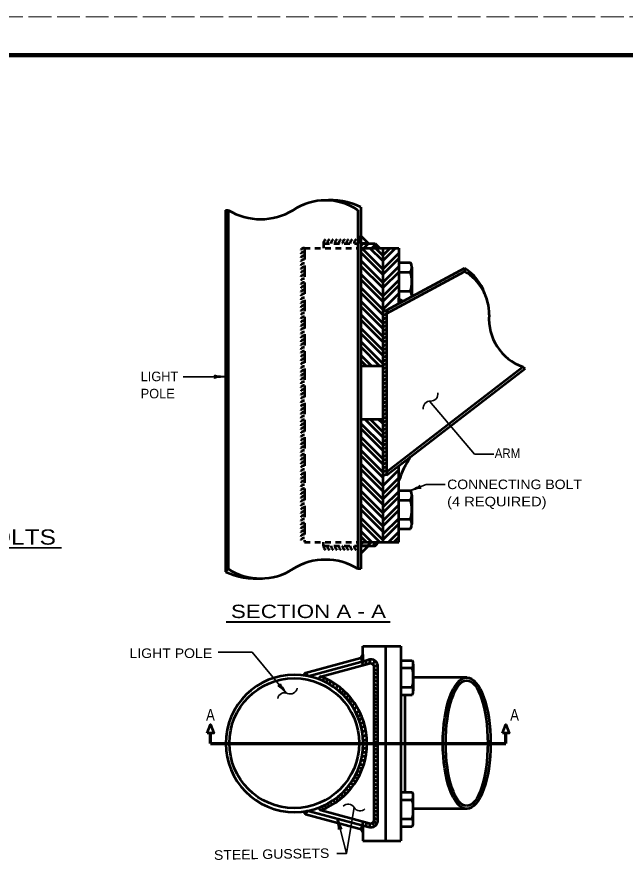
# Model space of a CAD drawing. Extents: x -1 to 679, y -228 to 440.
# Drawn here: x 356 to 515.4, y 218.8 to 440.2 of the extents above; entities that cross this region are included whole.
import ezdxf
from ezdxf.enums import TextEntityAlignment as Align

# ---------------------------------------------------------------- set-up
doc = ezdxf.new("R2010")
doc.units = 0
for name, pattern in [('LONG_DASHED', [7.5, 6, -1.5]), ('MEDIUM_DASHED', [4.5, 3, -1.5]), ('SHORT_DASHED', [2.7, 1.5, -1.2])]:
    doc.linetypes.add(name, pattern=pattern)
doc.layers.add('1', color=7, linetype='Continuous', lineweight=35)
doc.layers.add('61', color=7, linetype='Continuous', lineweight=35)

msp = doc.modelspace()

# ---------------------------------------------------------------- linework, layer by layer
at = {"layer": '1', "lineweight": 53}
for p, q in [((410.626, 389.642), (410.626, 294.892)), ((410.626, 389.642), (411.376, 389.642)), ((411.376, 389.642), (411.376, 295.642)), ((445.376, 389.642), (445.376, 295.642)), ((446.126, 380.892), (449.876, 380.892)), ((446.741, 380.892), (446.148, 380.299)), ((448.156, 380.892), (446.906, 379.642)), ((449.876, 380.892), (451.126, 379.642)), ((446.126, 379.642), (446.126, 295.642)), ((446.126, 379.642), (449.876, 379.642)), ((451.876, 374.173), (446.407, 379.642)), ((451.876, 376.295), (448.529, 379.642)), ((449.876, 380.491), (449.027, 379.642)), ((449.876, 379.642), (451.109, 379.642)), ((451.876, 377.709), (449.943, 379.642)), ((451.126, 379.642), (456.126, 379.642)), ((451.876, 379.642), (451.876, 302.642)), ((455.223, 379.642), (451.876, 376.295)), ((453.809, 379.642), (451.876, 377.709)), ((451.876, 372.759), (446.126, 378.509)), ((456.133, 378.43), (451.876, 374.173)), ((456.134, 377.017), (451.876, 372.759)), ((451.876, 370.638), (446.126, 376.388)), ((451.876, 369.223), (446.126, 374.973)), ((456.134, 374.895), (451.876, 370.638)), ((456.126, 375.892), (459.126, 375.892)), ((459.496, 374.642), (459.496, 367.093)), ((473.295, 374.387), (473.303, 373.544)), ((451.876, 367.102), (446.126, 372.852)), ((456.134, 373.481), (451.876, 369.223)), ((452.884, 362.549), (473.303, 373.544)), ((456.126, 373.392), (459.126, 373.392)), ((451.876, 365.688), (446.126, 371.438)), ((456.134, 371.36), (451.876, 367.102)), ((456.134, 369.945), (451.876, 365.688)), ((451.876, 363.566), (446.126, 369.316)), ((451.876, 362.152), (446.126, 367.902)), ((456.134, 367.824), (451.876, 363.566)), ((456.126, 368.392), (459.126, 368.392)), ((456.126, 368.392), (456.126, 365.142)), ((451.876, 360.031), (446.126, 365.781)), ((456.126, 365.142), (456.126, 366.507)), ((457.386, 365.82), (456.126, 365.142)), ((451.876, 358.616), (446.126, 364.366)), ((452.876, 363.392), (452.876, 320.142)), ((451.876, 356.495), (446.126, 362.245)), ((451.876, 355.081), (446.126, 360.831)), ((451.876, 352.959), (446.126, 358.709)), ((451.876, 351.545), (446.126, 357.295)), ((451.876, 349.424), (446.126, 355.174)), ((451.118, 348.767), (446.126, 353.759)), ((448.997, 348.767), (446.126, 351.638)), ((447.583, 348.767), (446.126, 350.224)), ((451.876, 348.767), (446.126, 348.767)), ((451.876, 334.767), (446.126, 334.767)), ((451.877, 330.145), (447.255, 334.767)), ((451.877, 331.56), (448.669, 334.767)), ((451.876, 333.681), (450.791, 334.767)), ((451.877, 326.61), (446.127, 332.36)), ((451.877, 328.024), (446.408, 333.492)), ((451.877, 324.488), (446.127, 330.238)), ((451.877, 323.074), (446.127, 328.824)), ((451.877, 320.953), (446.127, 326.703)), ((451.877, 319.538), (446.127, 325.288)), ((451.877, 317.417), (446.127, 323.167)), ((451.877, 316.003), (446.127, 321.753)), ((451.876, 317.416), (456.134, 321.674)), ((456.126, 318.779), (456.126, 322.642)), ((451.877, 313.881), (446.127, 319.631)), ((451.876, 315.295), (456.134, 319.553)), ((451.877, 312.467), (446.127, 318.217)), ((451.876, 313.881), (456.134, 318.138)), ((451.877, 310.346), (446.127, 316.096)), ((451.877, 308.931), (446.127, 314.681)), ((451.876, 311.759), (456.134, 316.017)), ((451.876, 310.345), (456.134, 314.603)), ((456.126, 316.142), (459.126, 316.142)), ((459.496, 314.892), (459.496, 307.343)), ((451.877, 306.81), (446.127, 312.56)), ((451.876, 308.224), (456.134, 312.481)), ((456.126, 313.642), (459.126, 313.642)), ((451.877, 305.396), (446.127, 311.146)), ((451.876, 306.809), (456.134, 311.067)), ((451.877, 303.274), (446.127, 309.024)), ((451.876, 304.688), (456.134, 308.946)), ((456.126, 308.642), (459.126, 308.642)), ((451.119, 302.617), (446.127, 307.61)), ((451.877, 303.274), (456.134, 307.531)), ((456.126, 306.142), (459.126, 306.142)), ((448.998, 302.617), (446.127, 305.489)), ((447.583, 302.617), (446.127, 304.074)), ((453.365, 302.642), (456.134, 305.41)), ((454.78, 302.642), (456.134, 303.996)), ((446.126, 301.642), (449.876, 301.642)), ((446.133, 302.06), (446.716, 302.642)), ((447.854, 301.659), (448.837, 302.642)), ((449.268, 301.659), (449.876, 302.266)), ((449.876, 301.642), (450.724, 302.642)), ((410.626, 294.892), (411.376, 295.642)), ((446.126, 295.642), (445.376, 295.642)), ((446.626, 275.411), (456.626, 275.411)), ((452.626, 275.411), (452.626, 224.373)), ((456.626, 275.411), (456.626, 224.373)), ((446.115, 272.274), (446.626, 273.173)), ((431.626, 268.392), (446.115, 272.274)), ((432.301, 267.537), (448.058, 271.759)), ((435.706, 267.414), (448.316, 270.793)), ((456.626, 271.661), (459.626, 271.661)), ((459.876, 270.661), (459.876, 263.661)), ((431.626, 268.392), (431.108, 267.737)), ((431.626, 268.392), (432.301, 267.537)), ((449.626, 229.892), (449.626, 269.892)), ((450.626, 229.892), (450.626, 269.892)), ((456.626, 269.661), (459.626, 269.661)), ((473.876, 267.161), (459.876, 267.161)), ((456.626, 264.661), (459.626, 264.661)), ((456.626, 262.661), (459.626, 262.661)), ((457.626, 262.661), (457.626, 237.123)), ((456.626, 237.123), (459.626, 237.123)), ((456.626, 235.123), (459.626, 235.123)), ((459.876, 229.123), (459.876, 236.123)), ((473.876, 232.758), (459.876, 232.758)), ((431.626, 231.392), (431.108, 232.046)), ((431.626, 231.392), (432.301, 232.246)), ((431.626, 231.392), (446.598, 227.38)), ((432.301, 232.246), (448.058, 228.024)), ((435.706, 232.369), (448.316, 228.99)), ((446.115, 227.51), (446.626, 228.408)), ((446.626, 228.408), (446.626, 224.373)), ((446.626, 226.611), (446.626, 228.408)), ((456.626, 230.123), (459.626, 230.123)), ((456.626, 228.123), (459.626, 228.123)), ((446.626, 224.373), (456.626, 224.373))]:
    msp.add_line(p, q, dxfattribs=at)
at = {"layer": '1', "linetype": 'SHORT_DASHED', "lineweight": 53}
for p, q in [((436.376, 380.892), (445.376, 380.892)), ((436.376, 380.892), (436.376, 379.642)), ((431.376, 379.642), (445.376, 379.642)), ((431.376, 302.642), (445.376, 302.642)), ((436.376, 301.642), (436.376, 302.642)), ((436.376, 301.642), (445.376, 301.642))]:
    msp.add_line(p, q, dxfattribs=at)
at = {"layer": '1', "lineweight": 13}
msp.add_line((445.376, 381.892), (445.376, 380.892), dxfattribs=at)
at = {"layer": '1', "linetype": 'MEDIUM_DASHED', "lineweight": 53}
msp.add_line((431.376, 379.642), (431.376, 302.642), dxfattribs=at)
at = {"layer": '1'}
for p, q in [((410.626, 345.959), (399.569, 345.959)), ((272.629, 301.175), (367.649, 301.175)), ((442.36, 221.027), (439.799, 221.027))]:
    msp.add_line(p, q, dxfattribs=at)
at = {"layer": '1', "lineweight": 40}
msp.add_line((410.805, 281.73), (453.86, 281.73), dxfattribs=at)
at = {"layer": '1', "lineweight": 70}
for p, q in [((406.734, 249.892), (406.734, 252.543)), ((484.126, 249.892), (484.126, 252.543)), ((406.734, 249.892), (484.126, 249.892))]:
    msp.add_line(p, q, dxfattribs=at)
at = {"layer": '1', "lineweight": 53}
for points in [[(446.126, 390.392), (446.126, 380.892), (446.126, 379.642)], [(456.126, 379.642), (456.126, 375.892), (456.126, 373.392), (456.126, 368.392)], [(452.876, 363.392), (456.126, 365.142), (473.295, 374.387)], [(452.876, 321.088), (488.562, 348.539), (489.218, 348.097)], [(452.876, 320.142), (459.141, 324.961), (489.218, 348.097)], [(456.126, 302.642), (456.126, 322.642), (459.141, 324.961)], [(446.126, 302.642), (450.724, 302.642), (456.126, 302.642)], [(446.626, 271.376), (446.626, 273.173), (446.626, 275.411)], [(431.108, 267.737), (431.626, 268.392), (432.301, 267.537)], [(431.108, 232.046), (431.626, 231.392), (432.301, 232.246)]]:
    msp.add_lwpolyline(points, dxfattribs=at)
for points in [[(446.126, 380.892), (446.126, 382.892), (448.126, 380.892)], [(449.876, 380.892), (451.126, 379.642), (449.876, 379.642)], [(446.126, 301.642), (446.126, 299.642), (448.126, 301.642)], [(449.876, 302.642), (450.724, 302.642), (449.876, 301.642)], [(446.115, 272.274), (446.626, 273.173), (446.626, 271.376)], [(405.879, 252.543), (406.734, 254.892), (407.589, 252.543)], [(483.271, 252.543), (484.126, 254.892), (484.981, 252.543)], [(446.115, 227.51), (446.626, 228.408), (446.626, 226.611)]]:
    msp.add_lwpolyline(points, close=True, dxfattribs=at)
at = {"layer": '1'}
for points in [[(464.152, 339.582), (475.94, 325.7), (480.976, 325.7)], [(459.126, 316.142), (463.29, 317.713), (468.202, 317.713)], [(426.552, 263.065), (417.634, 273.818), (408.716, 273.818)], [(444.352, 233.162), (442.36, 221.027), (439.977, 230.209)]]:
    msp.add_lwpolyline(points, dxfattribs=at)
at = {"layer": '1', "lineweight": 53}
msp.add_circle((428.677, 249.951), 17, dxfattribs=at)
for centre, radius, start, end in [((436.876, 376.588), 15.577, 56.92912, 123.07088), ((438.002, 373.339), 18.889, 64.52845, 94.9624), ((419.876, 403.543), 16.294, 238.55651, 301.44349), ((457.2, 374.642), 2.296, 327.01247, 32.98752), ((467.138, 364.06), 12.023, 17.99602, 59.19333), ((450.816, 370.892), 8.678, 343.25701, 16.74299), ((467.05, 362.494), 12.696, 358.41667, 60.49676), ((457.2, 367.142), 2.296, 355.26426, 32.98752), ((457.431, 367.401), 1.581, 214.41854, 268.39893), ((493.112, 361.151), 13.407, 175.75547, 250.16391), ((480.425, 310.754), 25.59, 146.27638, 161.72396), ((457.2, 314.892), 2.296, 327.01247, 32.98752), ((450.816, 311.142), 8.678, 343.25701, 16.74299), ((457.2, 307.392), 2.296, 327.01248, 32.98753), ((436.876, 281.74), 16.294, 58.55651, 121.44349), ((418.75, 311.945), 18.889, 244.52845, 274.9624), ((419.876, 308.695), 15.577, 236.92912, 303.07088), ((447.261, 270.975), 0.751, 147.77643, 229.06692), ((446.744, 271.06), 0.751, 320.93308, 42.22357), ((448.736, 269.993), 1.893, 356.94754, 111.01297), ((447.834, 271.484), 0.751, 308.93308, 30.22357), ((448.648, 269.873), 0.978, 1.08363, 109.83034), ((449.051, 271.557), 0.751, 275.93308, 357.22357), ((449.963, 270.964), 0.751, 243.93308, 325.22357), ((457.751, 270.661), 2.125, 331.92751, 28.07249), ((450.109, 269.918), 0.751, 228.93308, 310.22357), ((450.109, 268.971), 0.751, 228.93308, 310.22357), ((447.251, 267.161), 12.625, 348.57881, 11.42119), ((428.734, 249.895), 18, 78.57153, 78.56832), ((428.734, 249.895), 18, 78.56832, 82.41957), ((435.826, 266.807), 0.619, 101.14958, 189.27426), ((428.956, 249.892), 18.778, 291.06711, 68.93288), ((436.875, 266.413), 0.619, 101.14958, 189.27426), ((437.76, 265.987), 0.619, 101.14958, 189.27426), ((438.58, 265.528), 0.619, 101.14958, 189.27426), ((450.109, 267.989), 0.751, 228.93308, 310.22357), ((450.144, 267.042), 0.751, 228.93308, 310.22357), ((439.432, 265.003), 0.619, 101.14958, 189.27426), ((440.317, 264.38), 0.619, 101.14958, 189.27426), ((441.104, 263.724), 0.619, 101.14958, 189.27426), ((441.793, 263.101), 0.619, 101.14958, 189.27426), ((450.109, 266.024), 0.751, 228.93308, 310.22357), ((450.109, 265.042), 0.751, 228.93308, 310.22357), ((450.109, 264.095), 0.751, 228.93308, 310.22357), ((457.751, 263.661), 2.125, 331.92751, 28.07249), ((442.383, 262.51), 0.619, 101.14958, 189.27426), ((442.974, 261.704), 0.619, 94.14958, 182.27426), ((443.596, 261.081), 0.619, 94.14958, 203.72751), ((450.144, 263.218), 0.751, 228.93308, 310.22357), ((450.161, 262.376), 0.751, 228.93308, 310.22357), ((444.055, 260.393), 0.619, 94.14958, 182.27426), ((444.547, 259.638), 0.619, 94.14958, 182.27426), ((445.077, 258.736), 0.619, 82.14958, 170.27426), ((450.126, 260.727), 0.751, 228.93308, 310.22357), ((450.144, 261.569), 0.751, 228.93308, 310.22357), ((450.161, 259.797), 0.751, 228.93308, 310.22357), ((445.601, 257.621), 0.619, 82.14958, 170.27426), ((446.027, 256.702), 0.619, 82.14958, 170.27426), ((450.126, 257.885), 0.751, 228.93308, 310.22357), ((450.144, 258.832), 0.751, 228.93308, 310.22357), ((446.421, 255.751), 0.619, 82.14958, 170.27426), ((446.716, 254.734), 0.619, 82.14958, 170.27426), ((450.144, 257.043), 0.751, 228.93308, 310.22357), ((450.144, 256.236), 0.751, 228.93308, 310.22357), ((450.161, 255.447), 0.751, 228.93308, 310.22357), ((446.911, 253.647), 0.619, 69.14958, 157.27426), ((447.174, 252.564), 0.619, 69.14958, 157.27426), ((450.144, 254.587), 0.751, 228.93308, 310.22357), ((450.161, 253.763), 0.751, 228.93308, 310.22357), ((447.305, 251.318), 0.619, 69.14958, 157.27426), ((447.226, 250.128), 0.619, 48.14958, 136.27426), ((450.114, 251.911), 0.751, 228.93308, 310.22357), ((450.137, 252.813), 0.751, 228.93308, 310.22357), ((450.137, 251.033), 0.751, 228.93308, 310.22357), ((447.193, 247.963), 0.619, 48.14958, 136.27426), ((447.226, 249.078), 0.619, 48.14958, 136.27426), ((450.114, 250.059), 0.751, 228.93308, 310.22357), ((450.114, 249.133), 0.751, 228.93308, 310.22357), ((446.779, 245.893), 0.619, 31.14958, 119.27426), ((446.998, 246.913), 0.619, 31.14958, 119.27426), ((450.114, 248.184), 0.751, 228.93308, 310.22357), ((450.137, 247.21), 0.751, 228.93308, 310.22357), ((446.16, 243.711), 0.619, 23.14958, 111.27426), ((446.571, 244.827), 0.619, 31.14958, 119.27426), ((450.114, 245.097), 0.751, 228.93308, 310.22357), ((450.161, 246.142), 0.751, 228.93308, 310.22357), ((444.971, 241.139), 0.619, 15.14958, 103.27426), ((445.45, 241.935), 0.619, 23.14958, 111.27426), ((445.864, 242.764), 0.619, 23.14958, 111.27426), ((450.114, 241.964), 0.751, 228.93308, 310.22357), ((450.161, 244.053), 0.751, 228.93308, 310.22357), ((450.161, 242.985), 0.751, 228.93308, 310.22357), ((443.521, 238.711), 0.619, 15.14958, 103.27426), ((444.083, 239.569), 0.619, 15.14958, 103.27426), ((444.616, 240.339), 0.619, 15.14958, 103.27426), ((450.161, 240.895), 0.751, 228.93308, 310.22357), ((450.161, 239.875), 0.751, 228.93308, 310.22357), ((441.547, 236.562), 0.619, 3.14958, 91.27426), ((442.198, 237.361), 0.619, 3.14958, 91.27426), ((442.82, 238.013), 0.619, 3.14958, 91.27426), ((450.131, 237.86), 0.751, 228.93308, 310.22357), ((450.192, 238.867), 0.751, 228.93308, 310.22357), ((457.751, 236.123), 2.125, 331.92751, 28.07249), ((438.69, 234.374), 0.619, 352.14958, 80.27426), ((439.43, 234.848), 0.619, 352.14958, 80.27426), ((440.081, 235.351), 0.619, 352.14958, 80.27426), ((440.733, 235.973), 0.619, 352.14958, 80.27426), ((450.1, 236.883), 0.751, 228.93308, 310.22357), ((450.161, 235.815), 0.751, 228.93308, 310.22357), ((447.251, 232.623), 12.625, 348.57881, 11.42119), ((435.826, 232.977), 0.619, 168.16306, 258.85042), ((435.553, 232.716), 0.619, 352.14958, 80.27426), ((436.382, 233.042), 0.619, 352.14958, 80.27426), ((437.151, 233.515), 0.619, 352.14958, 80.27426), ((437.891, 233.93), 0.619, 352.14958, 80.27426), ((450.161, 234.808), 0.751, 228.93308, 310.22357), ((450.192, 233.831), 0.751, 228.93308, 310.22357), ((428.734, 249.889), 18, 277.58043, 281.43168), ((450.161, 231.908), 0.751, 228.93308, 310.22357), ((450.271, 230.907), 0.751, 218.93308, 300.22357), ((450.222, 232.885), 0.751, 228.93308, 310.22357), ((447.305, 228.728), 0.751, 123.93308, 205.22357), ((448.22, 228.499), 0.751, 123.93308, 205.22357), ((448.736, 229.791), 1.893, 248.98703, 3.05246), ((448.648, 229.91), 0.978, 250.16966, 358.91637), ((449.157, 228.517), 0.751, 145.93308, 227.22357), ((450.062, 228.961), 0.751, 166.93308, 248.22357), ((450.362, 229.798), 0.751, 191.93308, 273.22357), ((457.751, 229.123), 2.125, 331.92751, 28.07249)]:
    msp.add_arc(centre, radius, start, end, dxfattribs=at)
at = {"layer": '1', "linetype": 'SHORT_DASHED', "lineweight": 53}
for centre, start, end in [((437.312, 381.049), 117.33592, 189.53397), ((438.312, 381.049), 117.33592, 189.53397), ((439.312, 381.049), 117.33592, 189.53397), ((440.312, 381.049), 117.33592, 189.53397), ((441.312, 381.049), 117.33592, 189.53397), ((442.312, 381.049), 117.33592, 189.53397), ((443.312, 381.049), 117.33592, 189.53397), ((444.312, 381.049), 117.33592, 189.53397), ((445.312, 381.049), 117.33592, 189.53397), ((431.219, 378.706), 80.46603, 152.66408), ((431.219, 378.706), 80.46603, 152.66408), ((431.219, 377.706), 80.46603, 152.66408), ((431.219, 376.706), 80.46603, 152.66408), ((431.219, 375.706), 80.46603, 152.66408), ((431.219, 374.706), 80.46603, 152.66408), ((431.219, 373.706), 80.46603, 152.66408), ((431.219, 372.706), 80.46603, 152.66408), ((431.219, 371.706), 80.46603, 152.66408), ((431.219, 370.706), 80.46603, 152.66408), ((431.219, 369.706), 80.46603, 152.66408), ((431.219, 368.706), 80.46603, 152.66408), ((431.219, 367.706), 80.46603, 152.66408), ((431.219, 366.706), 80.46603, 152.66408), ((431.219, 365.706), 80.46603, 152.66408), ((431.219, 364.706), 80.46603, 152.66408), ((431.219, 363.706), 80.46603, 152.66408), ((431.219, 362.706), 80.46603, 152.66408), ((452.719, 362.303), 80.46603, 152.66408), ((431.219, 361.706), 80.46603, 152.66408), ((431.219, 360.706), 80.46603, 152.66408), ((452.719, 361.303), 80.46603, 152.66408), ((452.719, 360.303), 80.46603, 152.66408), ((431.219, 359.706), 80.46603, 152.66408), ((431.219, 358.706), 80.46603, 152.66408), ((452.719, 359.303), 80.46603, 152.66408), ((452.719, 358.303), 80.46603, 152.66408), ((431.219, 357.706), 80.46603, 152.66408), ((431.219, 356.706), 80.46603, 152.66408), ((431.219, 355.706), 80.46603, 152.66408), ((452.719, 357.303), 80.46603, 152.66408), ((452.719, 356.303), 80.46603, 152.66408), ((431.219, 354.706), 80.46603, 152.66408), ((431.219, 353.706), 80.46603, 152.66408), ((452.719, 355.303), 80.46603, 152.66408), ((452.719, 354.303), 80.46603, 152.66408), ((431.219, 352.706), 80.46603, 152.66408), ((431.219, 351.706), 80.46603, 152.66408), ((452.719, 353.303), 80.46603, 152.66408), ((452.719, 352.303), 80.46603, 152.66408), ((452.719, 351.303), 80.46603, 152.66408), ((431.219, 350.706), 80.46603, 152.66408), ((431.219, 349.706), 80.46603, 152.66408), ((452.719, 350.303), 80.46603, 152.66408), ((452.719, 349.303), 80.46603, 152.66408), ((431.219, 348.706), 80.46603, 152.66408), ((431.219, 347.706), 80.46603, 152.66408), ((431.219, 346.706), 80.46603, 152.66408), ((452.719, 348.303), 80.46603, 152.66408), ((452.719, 347.303), 80.46603, 152.66408), ((431.219, 345.706), 80.46603, 152.66408), ((431.219, 344.706), 80.46603, 152.66408), ((452.719, 346.303), 80.46603, 152.66408), ((452.719, 345.303), 80.46603, 152.66408), ((431.219, 343.706), 80.46603, 152.66408), ((431.219, 342.706), 80.46603, 152.66408), ((452.719, 344.303), 80.46603, 152.66408), ((452.719, 343.303), 80.46603, 152.66408), ((452.719, 342.303), 80.46603, 152.66408), ((431.219, 341.706), 80.46603, 152.66408), ((431.219, 340.706), 80.46603, 152.66408), ((452.719, 341.303), 80.46603, 152.66408), ((452.719, 340.303), 80.46603, 152.66408), ((431.219, 339.706), 80.46603, 152.66408), ((431.219, 338.706), 80.46603, 152.66408), ((452.719, 339.303), 80.46603, 152.66408), ((452.719, 338.303), 80.46603, 152.66408), ((431.219, 337.706), 80.46603, 152.66408), ((431.219, 336.706), 80.46603, 152.66408), ((431.219, 335.706), 80.46603, 152.66408), ((452.719, 337.303), 80.46603, 152.66408), ((452.719, 336.303), 80.46603, 152.66408), ((431.219, 334.706), 80.46603, 152.66408), ((431.219, 333.706), 80.46603, 152.66408), ((452.719, 335.303), 80.46603, 152.66408), ((452.719, 334.303), 80.46603, 152.66408), ((431.219, 332.706), 80.46603, 152.66408), ((431.219, 331.706), 80.46603, 152.66408), ((452.719, 333.303), 80.46603, 152.66408), ((452.719, 332.303), 80.46603, 152.66408), ((452.719, 331.303), 80.46603, 152.66408), ((431.219, 330.706), 80.46603, 152.66408), ((431.219, 329.706), 80.46603, 152.66408), ((452.719, 330.303), 80.46603, 152.66408), ((452.719, 329.303), 80.46603, 152.66408), ((431.219, 328.706), 80.46603, 152.66408), ((431.219, 327.706), 80.46603, 152.66408), ((452.719, 328.303), 80.46603, 152.66408), ((452.719, 327.303), 80.46603, 152.66408), ((431.219, 326.706), 80.46603, 152.66408), ((431.219, 325.706), 80.46603, 152.66408), ((431.219, 324.706), 80.46603, 152.66408), ((452.719, 326.303), 80.46603, 152.66408), ((452.719, 325.303), 80.46603, 152.66408), ((431.219, 323.706), 80.46603, 152.66408), ((431.219, 322.706), 80.46603, 152.66408), ((452.719, 324.303), 80.46603, 152.66408), ((452.719, 323.303), 80.46603, 152.66408), ((431.219, 321.706), 80.46603, 152.66408), ((431.219, 320.706), 80.46603, 152.66408), ((452.719, 322.303), 80.46603, 152.66408), ((452.719, 321.303), 80.46603, 152.66408), ((452.719, 320.303), 80.46603, 152.66408), ((431.219, 319.706), 80.46603, 152.66408), ((431.219, 318.706), 80.46603, 152.66408), ((452.719, 319.303), 80.46603, 152.66408), ((431.219, 317.706), 80.46603, 152.66408), ((431.219, 316.706), 80.46603, 152.66408), ((431.219, 315.706), 80.46603, 152.66408), ((431.219, 314.706), 80.46603, 152.66408), ((431.219, 313.706), 80.46603, 152.66408), ((431.219, 312.706), 80.46603, 152.66408), ((431.219, 311.706), 80.46603, 152.66408), ((431.219, 310.706), 80.46603, 152.66408), ((431.219, 309.706), 80.46603, 152.66408), ((431.219, 308.706), 80.46603, 152.66408), ((431.219, 307.706), 80.46603, 152.66408), ((431.219, 306.706), 80.46603, 152.66408), ((431.219, 305.706), 80.46603, 152.66408), ((431.219, 304.706), 80.46603, 152.66408), ((431.219, 303.706), 80.46603, 152.66408), ((431.219, 302.706), 80.46603, 152.66408), ((437.312, 301.485), 170.46602, 242.66408), ((438.312, 301.485), 170.46602, 242.66408), ((439.312, 301.485), 170.46602, 242.66408), ((440.312, 301.485), 170.46602, 242.66408), ((441.312, 301.485), 170.46602, 242.66408), ((442.312, 301.485), 170.46602, 242.66408), ((443.312, 301.485), 170.46602, 242.66408), ((444.312, 301.485), 170.46602, 242.66408), ((445.312, 301.485), 170.46602, 242.66408)]:
    msp.add_arc(centre, 0.949, start, end, dxfattribs=at)
at = {"layer": '1'}
for centre, start, end in [((464.494, 341.415), 266.90049, 10.06203), ((464.296, 337.755), 86.90049, 190.06203), ((427.645, 264.688), 245.90049, 349.06203), ((426.148, 261.342), 65.90049, 169.06203), ((442.807, 232.134), 31.90049, 135.06203), ((445.919, 234.071), 211.90049, 315.06203)]:
    msp.add_arc(centre, 1.833, start, end, dxfattribs=at)
at = {"layer": '1', "lineweight": 40}
for centre, major_axis, ratio, start_param, end_param in [((409.535, 345.683), (1.786, 0.156), 0.122415, 0.8963533, 3.1415927), ((409.505, 346.171), (-1.756, 0.176), 0.07063, 6.2823074, 8.5597026), ((460.049, 316.786), (-1.616, -0.776), 0.122415, 0.8963533, 3.1415927), ((460.249, 316.339), (-1.705, -0.456), 0.07063, 3.1407148, 5.41811), ((425.642, 263.729), (1.26, -1.275), 0.122415, 0.8963533, 3.1415927), ((425.999, 264.063), (0.986, -1.464), 0.07063, 3.1407148, 5.41811), ((440.054, 229.071), (0.271, -1.744), 0.07063, 6.2823074, 8.5597026), ((440.519, 229.222), (-0.6, 1.689), 0.122415, 0.8963533, 3.1415927)]:
    msp.add_ellipse(centre, major_axis=major_axis, ratio=ratio, start_param=start_param, end_param=end_param, dxfattribs=at)
at = {"layer": '1', "lineweight": 53}
for major_axis, ratio in [((0, -17.202), 0.363338), ((0, -16.452), 0.334314)]:
    msp.add_ellipse((473.876, 249.959), major_axis=major_axis, ratio=ratio, dxfattribs=at)
at = {"layer": '61', "linetype": 'LONG_DASHED', "lineweight": 13}
msp.add_line((-0.979, 440.237), (679.041, 440.237), dxfattribs=at)
at = {"layer": '61', "lineweight": 158}
msp.add_lwpolyline([(668.061, 430.237), (29.021, 430.237), (29.021, 10.217)], dxfattribs=at)

# ---------------------------------------------------------------- texts
at = {"layer": '1'}
for s, p in [('LIGHT', (388.436, 344.798)), ('POLE', (388.436, 340.298))]:
    msp.add_text(s, height=2.5, dxfattribs=at).set_placement(p)
for s, height, width, p in [('ARM', 2.5, 0.9, (481.221, 324.667)), ('CONNECTING BOLT', 2.5, 1.1, (468.743, 316.515)), ('(4 REQUIRED)', 2.5, 1.15, (468.743, 312.015)), ('SECTION A - A', 3.5, 1.25, (412.098, 282.742)), ('LIGHT POLE', 2.5, 1.1, (385.498, 272.271)), ('A', 3, 0.85, (405.58, 255.892)), ('A', 3, 0.85, (485.28, 255.892))]:
    msp.add_text(s, height=height, dxfattribs=dict(at, width=width)).set_placement(p)
at = {"layer": '1', "width": 1.2}
msp.add_text('ARM ATTACHMENT - 2 BOLTS', height=4, dxfattribs=at).set_placement((320.218, 301.968), align=Align.CENTER)
at = {"layer": '1', "width": 1.1}
msp.add_text('STEEL GUSSETS', height=2.5, rotation=1, dxfattribs=at).set_placement((407.652, 219.382))

doc.saveas('drawing.dxf')
